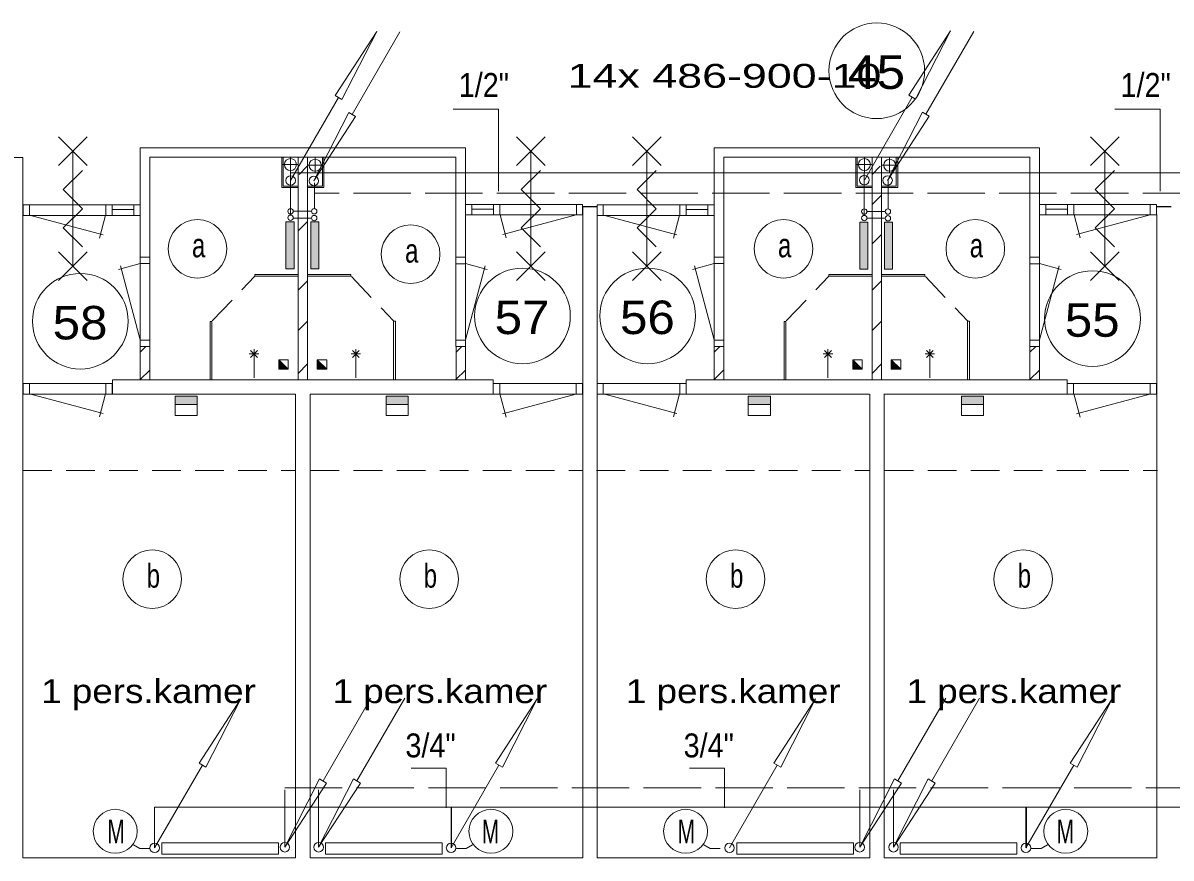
# Model space of a CAD drawing. Extents: x 295824 to 414724, y 24924 to 109024.
# Drawn here: x 308090 to 320090, y 30932 to 39664 of the extents above; entities that cross this region are included whole.
import ezdxf
from ezdxf.enums import TextEntityAlignment as Align

# ---------------------------------------------------------------- set-up
doc = ezdxf.new("R2010")
doc.units = 0
doc.header["$LTSCALE"] = 100
for name, pattern in [('DOT_DASHED', [7.7, 5, -1.2, 0.3, -1.2]), ('LONG_DASHED', [7.5, 6, -1.5]), ('MEDIUM_DASHED', [4.5, 3, -1.5])]:
    doc.linetypes.add(name, pattern=pattern)
doc.layers.add('16', color=7, linetype='Continuous', lineweight=13)
doc.layers.add('61', color=7, linetype='Continuous', lineweight=13)

msp = doc.modelspace()

# ---------------------------------------------------------------- hatches: boundary and pattern name
at = {"layer": '16'}
for points in [[(310838.6, 37093.5), (310924, 37093.5), (310924, 37585.6), (310838.6, 37585.6)], [(311097.8, 37093.5), (311183.2, 37093.5), (311183.2, 37585.6), (311097.8, 37585.6)], [(316835.4, 37090.3), (316920.8, 37090.3), (316920.8, 37582.5), (316835.4, 37582.5)], [(317094.6, 37090.3), (317180, 37090.3), (317180, 37582.5), (317094.6, 37582.5)], [(309911.3, 35760.1), (309679.8, 35760.1), (309679.8, 35673.6), (309911.3, 35673.6)], [(312117.3, 35760.1), (311885.8, 35760.1), (311885.8, 35673.6), (312117.3, 35673.6)], [(315902.2, 35760.1), (315670.7, 35760.1), (315670.7, 35673.6), (315902.2, 35673.6)], [(318129.9, 35760.1), (317898.4, 35760.1), (317898.4, 35673.6), (318129.9, 35673.6)]]:
    msp.add_hatch(color=256, dxfattribs=at).paths.add_polyline_path(points)
at = {"layer": '61'}
for points in [[(310763.1, 36143.3), (310863.1, 36043.3), (310763.1, 36043.3)], [(311166.2, 36143.3), (311266.2, 36043.3), (311166.2, 36043.3)], [(316762.3, 36143.3), (316862.3, 36043.3), (316762.3, 36043.3)], [(317165.4, 36143.3), (317265.4, 36043.3), (317165.4, 36043.3)]]:
    msp.add_hatch(color=256, dxfattribs=at).paths.add_polyline_path(points)

# ---------------------------------------------------------------- linework, layer by layer
at = {"layer": '16'}
for p, q in [((312030.4, 39571.3), (311530.4, 38705.3)), ((318027.2, 39575.8), (317527.2, 38709.8)), ((310887.4, 38017), (311387.4, 38883)), ((316884.2, 38021.5), (317384.2, 38887.5)), ((326194, 38096.3), (310885.9, 38096.3)), ((310885.9, 38096.3), (310885.9, 37659.8)), ((316882.7, 38096.3), (316882.7, 37656.7)), ((311106.2, 37624.5), (310914.5, 37624.5)), ((317103, 37621.3), (316911.2, 37621.3)), ((309679.8, 35673.6), (309679.8, 35559.7)), ((311885.8, 35673.6), (311885.8, 35559.7)), ((315670.7, 35673.6), (315670.7, 35559.7)), ((317898.4, 35673.6), (317898.4, 35559.7)), ((311727, 32603.9), (311227, 31737.9)), ((312080.5, 32603.9), (311580.5, 31737.9)), ((317735.5, 32603.9), (317235.5, 31737.9)), ((318088.9, 32603.9), (317588.9, 31737.9)), ((309466.3, 31039), (309966.3, 31905)), ((312564.8, 31039), (313064.8, 31905)), ((315474.7, 31039), (315974.7, 31905)), ((318573.2, 31039), (319073.2, 31905)), ((309466.3, 31465.3), (325376.7, 31465.3)), ((312564.7, 31038.7), (312564.7, 31465.3)), ((312564.8, 31039), (312564.8, 31465.3)), ((312570.6, 31039), (312570.6, 31465.3)), ((318573.2, 31038.7), (318573.2, 31465.3)), ((318579.1, 31039), (318579.1, 31465.3))]:
    msp.add_line(p, q, dxfattribs=at)
at = {"layer": '16', "linetype": 'LONG_DASHED'}
for p, q in [((311137.1, 37992.6), (311137.1, 37721)), ((317133.8, 38015.5), (317133.8, 37717.8)), ((326394, 37884.5), (311137.1, 37884.5)), ((310914.6, 37695.2), (311106.1, 37695.2)), ((316911.4, 37692.1), (317102.9, 37692.1)), ((310827, 31665.3), (326394, 31665.3)), ((310827, 31044.9), (310827, 31665.3)), ((311180.5, 31044.9), (311180.5, 31665.3)), ((316835.5, 31044.9), (316835.5, 31665.3)), ((317188.9, 31044.9), (317188.9, 31665.3))]:
    msp.add_line(p, q, dxfattribs=at)
at = {"layer": '16'}
for points in [[(311787.4, 39576), (311423.4, 38862), (311351.4, 38904)], [(317784.2, 39580.5), (317420.2, 38866.5), (317348.2, 38908.5)], [(311130.4, 38012.3), (311494.4, 38726.3), (311566.4, 38684.3)], [(317127.2, 38016.8), (317491.2, 38730.8), (317563.2, 38688.8)], [(310838.6, 37093.5), (310924, 37093.5), (310924, 37585.6), (310838.6, 37585.6)], [(311097.8, 37093.5), (311183.2, 37093.5), (311183.2, 37585.6), (311097.8, 37585.6)], [(316835.4, 37090.3), (316920.8, 37090.3), (316920.8, 37582.5), (316835.4, 37582.5)], [(317094.6, 37090.3), (317180, 37090.3), (317180, 37582.5), (317094.6, 37582.5)], [(309911.3, 35760.1), (309679.8, 35760.1), (309679.8, 35673.6), (309911.3, 35673.6)], [(312117.3, 35760.1), (311885.8, 35760.1), (311885.8, 35673.6), (312117.3, 35673.6)], [(315902.2, 35760.1), (315670.7, 35760.1), (315670.7, 35673.6), (315902.2, 35673.6)], [(318129.9, 35760.1), (317898.4, 35760.1), (317898.4, 35673.6), (318129.9, 35673.6)], [(310366.3, 32598), (310002.3, 31884), (309930.3, 31926)], [(313464.8, 32598), (313100.8, 31884), (313028.8, 31926)], [(316374.7, 32598), (316010.7, 31884), (315938.7, 31926)], [(319473.2, 32598), (319109.2, 31884), (319037.2, 31926)], [(310827, 31044.9), (311191, 31758.9), (311263, 31716.9)], [(311180.5, 31044.9), (311544.5, 31758.9), (311616.5, 31716.9)], [(316835.5, 31044.9), (317199.5, 31758.9), (317271.5, 31716.9)], [(317188.9, 31044.9), (317552.9, 31758.9), (317624.9, 31716.9)], [(309542.9, 31092), (310762.2, 31092), (310762.2, 30974.1), (309542.9, 30974.1)], [(311251.1, 31092), (312470.5, 31092), (312470.5, 30974.1), (311251.1, 30974.1)], [(315551.3, 31092), (316770.7, 31092), (316770.7, 30974.1), (315551.3, 30974.1)], [(317259.6, 31092), (318478.9, 31092), (318478.9, 30974.1), (317259.6, 30974.1)]]:
    msp.add_lwpolyline(points, close=True, dxfattribs=at)
for points in [[(313059.6, 37906), (313059.6, 38763.6), (312585.2, 38763.6)], [(319977.3, 37906), (319977.3, 38763.6), (319502.9, 38763.6)], [(309911.3, 35673.6), (309911.3, 35559.7), (309679.8, 35559.7)], [(312117.3, 35673.6), (312117.3, 35559.7), (311885.8, 35559.7)], [(315902.2, 35673.6), (315902.2, 35559.7), (315670.7, 35559.7)], [(318129.9, 35673.6), (318129.9, 35559.7), (317898.4, 35559.7)], [(312514.5, 31457.4), (312514.5, 31870.9), (312147.2, 31870.9)], [(315422.4, 31457.4), (315422.4, 31870.9), (315055.1, 31870.9)], [(309466.3, 31039), (309466.3, 31465.3), (326194, 31465.3)], [(309414.8, 31033.7), (309312.2, 31033.7), (309245.8, 31072.1)], [(312620.4, 31033.7), (312722.9, 31033.7), (312789.4, 31072.1)], [(315376.1, 31033.7), (315273.6, 31033.7), (315207.1, 31072.1)], [(318628.8, 31033.7), (318731.4, 31033.7), (318797.8, 31072.1)]]:
    msp.add_lwpolyline(points, dxfattribs=at)
for centre, radius in [((310887.4, 38016.7), 50), ((311130.4, 38012.6), 50), ((316884.2, 38021.2), 50), ((317127.2, 38017.1), 50), ((310886.7, 37695.2), 27.9), ((311134.1, 37695.2), 27.9), ((316883.5, 37692.1), 27.9), ((317130.9, 37692.1), 27.9), ((310886.7, 37627.4), 27.9), ((311134.1, 37624.5), 27.9), ((316883.5, 37624.3), 27.9), ((317130.9, 37621.3), 27.9), ((309054.2, 31211.8), 229.9), ((312980.9, 31211.8), 229.9), ((315015.6, 31211.8), 229.9), ((318989.4, 31211.8), 229.9), ((309466.3, 31038.7), 50), ((310827, 31045.2), 50), ((311180.5, 31045.2), 50), ((312564.7, 31038.7), 50), ((315474.7, 31038.7), 50), ((316835.5, 31045.2), 50), ((317188.9, 31045.2), 50), ((318573.2, 31038.7), 50)]:
    msp.add_circle(centre, radius, dxfattribs=at)
at = {"layer": '61'}
for p, q in [((308760.6, 38472.2), (308460.6, 38172.2)), ((308460.6, 38472.2), (308760.6, 38172.2)), ((313548.3, 38472.2), (313248.3, 38172.2)), ((313248.3, 38472.2), (313548.3, 38172.2)), ((314759.8, 38472.2), (314459.8, 38172.2)), ((314459.8, 38472.2), (314759.8, 38172.2)), ((319547.5, 38472.2), (319247.5, 38172.2)), ((319247.5, 38472.2), (319547.5, 38172.2)), ((308610.6, 37122.2), (308610.6, 38322.2)), ((313398.3, 37122.2), (313398.3, 38322.2)), ((314609.8, 37122.2), (314609.8, 38322.2)), ((319397.5, 37122.2), (319397.5, 38322.2)), ((308090.1, 38258.6), (308090.1, 30933.6)), ((309415.2, 37214.4), (309415.2, 38259)), ((310796.9, 38259), (310796.9, 37942.5)), ((310811.2, 38259.3), (310811.2, 37957.6)), ((310965.2, 35934), (310965.2, 38259)), ((311061.5, 38165.1), (310976.2, 38079.8)), ((311065.2, 35934), (311065.2, 38259)), ((311219.4, 37958.9), (311219.4, 38257.9)), ((311234.4, 37943.9), (311234.4, 38257.6)), ((315414.4, 37214.4), (315414.4, 38259)), ((316795.9, 38259), (316795.9, 37942.5)), ((316810.2, 38259.3), (316810.2, 37957.6)), ((316964.4, 35934), (316964.4, 38259)), ((317050.8, 38165.1), (316965.5, 38079.8)), ((317064.4, 35934), (317064.4, 38259)), ((317218.4, 37958.9), (317218.4, 38257.9)), ((317233.4, 37943.9), (317233.4, 38257.6)), ((310965.4, 37942.5), (310796.9, 37942.5)), ((310811.2, 37957.6), (310964.5, 37957.6)), ((311219.4, 37958.9), (311065.4, 37958.9)), ((311234.4, 37943.9), (311066.6, 37943.9)), ((312715.2, 37216.6), (312715.2, 38003.7)), ((316964.4, 37942.5), (316795.9, 37942.5)), ((316810.2, 37957.6), (316963.6, 37957.6)), ((317218.4, 37958.9), (317064.4, 37958.9)), ((317233.4, 37943.9), (317065.6, 37943.9)), ((318714.4, 37216.6), (318714.4, 38003.7)), ((317063.9, 37864.2), (316965.5, 37765.7)), ((308156.7, 37763.1), (308156.7, 37653.1)), ((308956.7, 37763.1), (308956.7, 37653.1)), ((309023.7, 37763.1), (309023.7, 37653.1)), ((309024.5, 37712.3), (309249.2, 37712.3)), ((309249.2, 37763.1), (309249.2, 37653.1)), ((312781.6, 37767), (312781.6, 37657)), ((313006.3, 37716.2), (312781.6, 37716.2)), ((313007.1, 37767), (313007.1, 37657)), ((313074.1, 37767), (313074.1, 37657)), ((313874.1, 37767), (313874.1, 37657)), ((313939.9, 37746.4), (314089.9, 37746.4)), ((313940.1, 37742.2), (313940.1, 30933.6)), ((313940.1, 37742.2), (314090.1, 37742.2)), ((314090.1, 37742.2), (314090.1, 30933.6)), ((314155.9, 37763.1), (314155.9, 37653.1)), ((314955.9, 37763.1), (314955.9, 37653.1)), ((315022.9, 37763.1), (315022.9, 37653.1)), ((315023.7, 37712.3), (315248.4, 37712.3)), ((315248.4, 37763.1), (315248.4, 37653.1)), ((318780.8, 37767), (318780.8, 37657)), ((319005.4, 37716.2), (318780.8, 37716.2)), ((319006.2, 37767), (319006.2, 37657)), ((319073.2, 37767), (319073.2, 37657)), ((319873.2, 37767), (319873.2, 37657)), ((319939.7, 37746), (320089.7, 37746)), ((319939.7, 37742.2), (320089.7, 37742.2)), ((308159.3, 37652.9), (308926.6, 37447.3)), ((308953.9, 37655.1), (308888.9, 37412.4)), ((309315.2, 37214.4), (309315.2, 37659)), ((311064.8, 37589), (310966.3, 37490.5)), ((313076.9, 37659), (313142, 37416.2)), ((313871.5, 37656.8), (313104.2, 37451.2)), ((314158.5, 37652.9), (314925.8, 37447.3)), ((314953.1, 37655.1), (314888, 37412.4)), ((315314.4, 37214.4), (315314.4, 37659)), ((319076.1, 37659), (319141.1, 37416.2)), ((319870.7, 37656.8), (319103.4, 37451.2)), ((319940.1, 37658.6), (319940.1, 30932.2)), ((312615.2, 37553.7), (312615.2, 37216.6)), ((317063.9, 37452.7), (316965.5, 37354.2)), ((318614.4, 37553.7), (318614.4, 37216.6)), ((308760.6, 37272.2), (308460.6, 36972.2)), ((308460.6, 37272.2), (308760.6, 36972.2)), ((309315.2, 37215.2), (309315.2, 36280.4)), ((309415.2, 37214.4), (309315.2, 37214.4)), ((309415.2, 36280.4), (309415.2, 37214.4)), ((312615.4, 36280), (312615.4, 37214)), ((312615.4, 37214), (312715.4, 37214)), ((312715.4, 37214), (312715.4, 36280)), ((313548.3, 37272.2), (313248.3, 36972.2)), ((313248.3, 37272.2), (313548.3, 36972.2)), ((314759.8, 37272.2), (314459.8, 36972.2)), ((314459.8, 37272.2), (314759.8, 36972.2)), ((315314.4, 37215.2), (315314.4, 36280.4)), ((315414.4, 37214.4), (315314.4, 37214.4)), ((315414.4, 36280.4), (315414.4, 37214.4)), ((318614.6, 36280), (318614.6, 37214)), ((318614.6, 37214), (318714.6, 37214)), ((318714.6, 37214), (318714.6, 36280)), ((319547.5, 37272.2), (319247.5, 36972.2)), ((319247.5, 37272.2), (319547.5, 36972.2)), ((309315.5, 37148.4), (309088.2, 37087.5)), ((309315.5, 36351), (309108.6, 37123.2)), ((309415.1, 37147.4), (309315.8, 37147.4)), ((312615.5, 37147), (312714.8, 37147)), ((312715.1, 37148), (312942.4, 37087.1)), ((312715.1, 36350.6), (312922, 37122.8)), ((315314.7, 37148.4), (315087.4, 37087.5)), ((315314.7, 36351), (315107.8, 37123.2)), ((315414.3, 37147.4), (315315, 37147.4)), ((318614.7, 37147), (318714, 37147)), ((318714.3, 37148), (318941.6, 37087.1)), ((318714.3, 36350.6), (318921.2, 37122.8)), ((310514.2, 37033.2), (310964.3, 37033.2)), ((310514.2, 37015.2), (310514.2, 37033.2)), ((310514.2, 37015.2), (310964.3, 37015.2)), ((311064.8, 36969), (310966.3, 36870.5)), ((311065.6, 37033.2), (311515.9, 37033.2)), ((316513.4, 37033.2), (316963.5, 37033.2)), ((316513.4, 37015.2), (316513.4, 37033.2)), ((316513.4, 37015.2), (316963.5, 37015.2)), ((317063.9, 36969), (316965.5, 36870.5)), ((317064.8, 37033.2), (317515.1, 37033.2)), ((309315.1, 36613.5), (309315.1, 36723.9)), ((315314.3, 36613.5), (315314.3, 36723.9)), ((310046.7, 36541.2), (310046.7, 35936.4)), ((310064.7, 36541.2), (310046.7, 36541.2)), ((310064.7, 36541.2), (310064.7, 35936.4)), ((311064.8, 36546.5), (310966.3, 36448)), ((311964.5, 36547.3), (311964.5, 35938.9)), ((311982.5, 36547.3), (311964.5, 36547.3)), ((311982.5, 36547.3), (311982.5, 35938.9)), ((316045.9, 36541.2), (316045.9, 35936.4)), ((316063.9, 36541.2), (316045.9, 36541.2)), ((316063.9, 36541.2), (316063.9, 35936.4)), ((317063.9, 36546.5), (316965.5, 36448)), ((317963.7, 36547.3), (317963.7, 35938.9)), ((317981.7, 36547.3), (317963.7, 36547.3)), ((317981.7, 36547.3), (317981.7, 35938.9)), ((309370.9, 36278.7), (309314.2, 36222)), ((309414.8, 36280.4), (309314.7, 36280.4)), ((309315, 36280.4), (309315, 35934)), ((309415.4, 36347.4), (309315.2, 36347.4)), ((309414.8, 36280), (309414.8, 35933.6)), ((310505.1, 36152.8), (310505.1, 36252.8)), ((311569.6, 36152.8), (311569.6, 36252.8)), ((312615.2, 36347), (312715.4, 36347)), ((312615.4, 36280), (312715.4, 36280)), ((312672.8, 36278.7), (312616.1, 36222)), ((312616.4, 36280.4), (312616.4, 35934)), ((312715.2, 36280.4), (312715.2, 35934)), ((315370, 36278.7), (315313.4, 36222)), ((315414, 36280.4), (315313.9, 36280.4)), ((315314.2, 36280.4), (315314.2, 35934)), ((315414.6, 36347.4), (315314.4, 36347.4)), ((315414, 36280), (315414, 35933.6)), ((316504.3, 36152.8), (316504.3, 36252.8)), ((317568.8, 36152.8), (317568.8, 36252.8)), ((318614.4, 36347), (318714.6, 36347)), ((318614.6, 36280), (318714.6, 36280)), ((318671.9, 36278.7), (318615.3, 36222)), ((318615.6, 36280.4), (318615.6, 35934)), ((318714.3, 36280.4), (318714.3, 35934)), ((310455.1, 36202.8), (310555.1, 36202.8)), ((310469.8, 36167.4), (310540.5, 36238.1)), ((310469.8, 36238.1), (310540.5, 36167.4)), ((310505.1, 36152.8), (310505.1, 35952.8)), ((311519.6, 36202.8), (311619.6, 36202.8)), ((311534.2, 36167.4), (311605, 36238.1)), ((311534.2, 36238.1), (311605, 36167.4)), ((311569.6, 36152.8), (311569.6, 35952.8)), ((316454.3, 36202.8), (316554.3, 36202.8)), ((316468.9, 36167.4), (316539.7, 36238.1)), ((316468.9, 36238.1), (316539.7, 36167.4)), ((316504.3, 36152.8), (316504.3, 35952.8)), ((317518.8, 36202.8), (317618.8, 36202.8)), ((317533.4, 36167.4), (317604.1, 36238.1)), ((317533.4, 36238.1), (317604.1, 36167.4)), ((317568.8, 36152.8), (317568.8, 35952.8)), ((309414.6, 36034.7), (309314.2, 35934.3)), ((311064.8, 36098.9), (310966.3, 36000.4)), ((312715.1, 36034.7), (312614.7, 35934.3)), ((315413.8, 36034.7), (315313.4, 35934.3)), ((317063.9, 36098.9), (316965.5, 36000.4)), ((318714.3, 36034.7), (318613.9, 35934.3)), ((308090.8, 35894.5), (308090.8, 35784.1)), ((309021.6, 35894.5), (308090.8, 35894.5)), ((308156.7, 35894.8), (308156.7, 35784.8)), ((308956.7, 35894.8), (308956.7, 35784.8)), ((309023.7, 35894.8), (309023.7, 35784.8)), ((313005, 35934), (309414.8, 35934)), ((313005.9, 35892.8), (313005.8, 35782.8)), ((313008, 35892.5), (313938.8, 35892.5)), ((313072.8, 35892.8), (313072.9, 35782.8)), ((313872.8, 35892.8), (313872.8, 35782.8)), ((314090, 35894.5), (314090, 35784.1)), ((315020.8, 35894.5), (314090, 35894.5)), ((314155.9, 35894.8), (314155.9, 35784.8)), ((314955.9, 35894.8), (314955.9, 35784.8)), ((315022.9, 35894.8), (315022.9, 35784.8)), ((319004.1, 35934), (315414, 35934)), ((319005, 35892.8), (319005, 35782.8)), ((319007.2, 35892.5), (319937.9, 35892.5)), ((319072, 35892.8), (319072, 35782.8)), ((319872, 35892.8), (319872, 35782.8)), ((310940.2, 35784), (308090.9, 35784)), ((308159.3, 35784.7), (308926.6, 35579.1)), ((308953.9, 35786.8), (308888.9, 35544.1)), ((310940.2, 35784), (308997.8, 35784)), ((311090.2, 35784), (313150.2, 35784)), ((313075.7, 35784.8), (313140.7, 35542.1)), ((313870.3, 35782.7), (313103, 35577.1)), ((316939.4, 35784), (314090.1, 35784)), ((314158.5, 35784.7), (314925.8, 35579.1)), ((314953.1, 35786.8), (314888, 35544.1)), ((316939.4, 35784), (314997, 35784)), ((317089.4, 35784), (319149.4, 35784)), ((319074.9, 35784.8), (319139.9, 35542.1)), ((319869.4, 35782.7), (319102.2, 35577.1))]:
    msp.add_line(p, q, dxfattribs=at)
at = {"layer": '61', "linetype": 'DOT_DASHED'}
for p, q in [((310801.4, 38184.2), (310965.4, 38184.2)), ((310801.5, 38184.2), (310965.6, 38184.2)), ((310886.6, 38258.4), (310886.6, 38099.1)), ((311061.2, 38176.8), (311225.3, 38176.8)), ((311144, 38257.1), (311144, 38093)), ((316800.5, 38184.2), (316964.6, 38184.2)), ((316885.6, 38258.4), (316885.6, 38099.1)), ((317060.3, 38176.8), (317224.3, 38176.8)), ((317148.8, 38257.1), (317148.8, 38093))]:
    msp.add_line(p, q, dxfattribs=at)
at = {"layer": '61', "linetype": 'MEDIUM_DASHED'}
for p, q in [((310069, 36548.8), (310513, 37016.1)), ((311523.3, 37012.1), (311965.2, 36547.1)), ((316068.2, 36548.8), (316512.2, 37016.1)), ((317522.5, 37012.1), (317964.3, 36547.1)), ((308090.1, 34984.3), (310940.1, 34984.3)), ((311096.4, 34984.3), (313946.4, 34984.3)), ((314085.9, 34984.3), (316936, 34984.3)), ((317097.7, 34984.3), (319947.8, 34984.3))]:
    msp.add_line(p, q, dxfattribs=at)
at = {"layer": '61'}
for points in [[(312715.2, 37759), (312715.2, 38359), (309315.2, 38359), (309315.2, 37759)], [(318714.4, 37759), (318714.4, 38359), (315314.4, 38359), (315314.4, 37759)], [(308090.1, 38258.6), (307832.8, 38258.6), (307832.8, 37776.3)], [(310940.4, 38259), (309415.2, 38259), (309415.2, 37309)], [(312615.2, 37033.2), (312615.2, 38259), (310735.2, 38259)], [(316939.6, 38259), (315414.4, 38259), (315414.4, 37309)], [(318614.4, 37033.2), (318614.4, 38259), (316734.4, 38259)], [(308710.6, 37322.2), (308510.6, 37522.2), (308710.6, 37722.2), (308510.6, 37922.2), (308710.6, 38122.2)], [(313498.3, 37322.2), (313298.3, 37522.2), (313498.3, 37722.2), (313298.3, 37922.2), (313498.3, 38122.2)], [(314709.8, 37322.2), (314509.8, 37522.2), (314709.8, 37722.2), (314509.8, 37922.2), (314709.8, 38122.2)], [(319497.5, 37322.2), (319297.5, 37522.2), (319497.5, 37722.2), (319297.5, 37922.2), (319497.5, 38122.2)], [(311065.6, 37015.2), (311515.9, 37015.2), (311515.9, 37033.2)], [(317064.8, 37015.2), (317515.1, 37015.2), (317515.1, 37033.2)], [(310863.1, 36043.3), (310763.1, 36043.3), (310763.1, 36143.3)], [(311266.2, 36043.3), (311166.2, 36043.3), (311166.2, 36143.3)], [(316862.3, 36043.3), (316762.3, 36043.3), (316762.3, 36143.3)], [(317265.4, 36043.3), (317165.4, 36043.3), (317165.4, 36143.3)], [(309024.2, 35784.1), (309024.2, 35934), (309429.6, 35934)], [(311090.2, 35784), (313005, 35784), (313005, 35934)], [(313938.8, 35892.5), (313938.8, 35782.1), (313005.4, 35782.1)], [(315023.4, 35784.1), (315023.4, 35934), (315428.8, 35934)], [(317089.4, 35784), (319004.1, 35784), (319004.1, 35934)], [(319937.9, 35892.5), (319937.9, 35782.1), (319004.6, 35782.1)], [(308090.1, 30933.6), (310940.1, 30933.6), (310940.1, 35783.6)], [(313940.1, 30933.6), (311090.1, 30933.6), (311090.1, 35783.6)], [(314090.1, 30933.6), (316940.1, 30933.6), (316940.1, 35783.6)], [(319940.1, 30933.6), (317090.1, 30933.6), (317090.1, 35783.6)]]:
    msp.add_lwpolyline(points, dxfattribs=at)
for points in [[(308090.8, 37762.8), (308090.8, 37652.4), (309315.1, 37652.4), (309315.1, 37762.8)], [(313940, 37766.6), (313940, 37656.3), (312715.7, 37656.3), (312715.7, 37766.6)], [(314090.2, 37762.8), (314090.2, 37652.4), (315314.5, 37652.4), (315314.5, 37762.8)], [(319939.2, 37766.6), (319939.2, 37656.3), (318714.9, 37656.3), (318714.9, 37766.6)], [(310863.1, 36043.3), (310863.1, 36143.3), (310763.1, 36143.3)], [(310763.1, 36143.3), (310863.1, 36043.3), (310763.1, 36043.3)], [(311266.2, 36043.3), (311266.2, 36143.3), (311166.2, 36143.3)], [(311166.2, 36143.3), (311266.2, 36043.3), (311166.2, 36043.3)], [(316862.3, 36043.3), (316862.3, 36143.3), (316762.3, 36143.3)], [(316762.3, 36143.3), (316862.3, 36043.3), (316762.3, 36043.3)], [(317265.4, 36043.3), (317265.4, 36143.3), (317165.4, 36143.3)], [(317165.4, 36143.3), (317265.4, 36043.3), (317165.4, 36043.3)]]:
    msp.add_lwpolyline(points, close=True, dxfattribs=at)
for centre, radius in [((317013.9, 39164.1), 500), ((310885.9, 38183.5), 62.5), ((311144, 38176.7), 62.5), ((316885, 38183.5), 62.5), ((317148.8, 38176.7), 62.5), ((309914.6, 37302.8), 306.3), ((316039.6, 37302.8), 306.3), ((318044.2, 37302.8), 306.3), ((312141.9, 37247.1), 306.3), ((313311, 36600.8), 500), ((314619.5, 36600.8), 500), ((308689.4, 36545.1), 500), ((319269, 36573), 500), ((309441.3, 33848), 306.3), ((312336.8, 33848), 306.3), ((315538.5, 33848), 306.3), ((318545.3, 33848), 306.3)]:
    msp.add_circle(centre, radius, dxfattribs=at)

# ---------------------------------------------------------------- texts
at = {"layer": '16'}
for s, width, p in [('1/2"', 0.9, (312644.5, 38890.7)), ('14x 486-900-10', 1.4, (313783.2, 38986.1)), ('1/2"', 0.9, (319562.2, 38890.7)), ('3/4"', 0.9, (312087.5, 31984.8)), ('3/4"', 0.9, (314995.4, 31984.8)), ('M', 0.65, (308972, 31085.1)), ('M', 0.65, (312886, 31085.1)), ('M', 0.65, (314933.3, 31085.1)), ('M', 0.65, (318894.5, 31085.1))]:
    msp.add_text(s, height=250, dxfattribs=dict(at, width=width)).set_placement(p)
at = {"layer": '61'}
for s, width, p in [('45', 1.15, (317011, 38974.2)), ('57', 1.1, (313306.7, 36410.9)), ('56', 1.1, (314616.6, 36410.9)), ('55', 1.1, (319266.1, 36383.1)), ('58', 1.1, (308686.5, 36355.2))]:
    msp.add_text(s, height=350, dxfattribs=dict(at, width=width)).set_placement(p, align=Align.CENTER)
for s, width, p in [('a', 0.75, (309856.6, 37213.7)), ('a', 0.75, (312083.9, 37158)), ('a', 0.75, (315981.6, 37213.7)), ('a', 0.75, (317986.2, 37213.7)), ('b', 0.75, (309383.3, 33758.9)), ('b', 0.75, (312278.8, 33758.9)), ('b', 0.75, (315480.5, 33758.9)), ('b', 0.75, (318487.3, 33758.9)), ('1 pers.kamer', 1.15, (308280.3, 32552.1)), ('1 pers.kamer', 1.15, (311325.5, 32552.1)), ('1 pers.kamer', 1.15, (314392.1, 32552.1)), ('1 pers.kamer', 1.15, (317325.4, 32552.1))]:
    msp.add_text(s, height=250, dxfattribs=dict(at, width=width)).set_placement(p)

doc.saveas('drawing.dxf')
